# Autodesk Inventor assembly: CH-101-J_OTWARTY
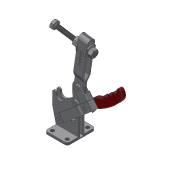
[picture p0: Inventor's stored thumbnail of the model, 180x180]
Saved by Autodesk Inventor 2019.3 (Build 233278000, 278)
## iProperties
Company: Î¢ÈíÖÐ¹ú
Created: 2012-09
Part Number: CH-101-J_OTWARTY
Material: Ogólny
Description: STEP AP203
Document SubType Name: Assembly
Designer: CADENGINEERING4
Sending System: SolidWorks 2010
Preprocessor: SwSTEP 2.0
Title: CH-101-J.STEP
Author: Î¢ÈíÓÃ»§
Revision Number: ÈÎºÎ
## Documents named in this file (16)
- D:\Vault_2016\Projekty\NASZ KATALOG\CLAMPTEK\STRONA\Vertical toggle clamp\CH-101-J\CH-101-J_OTWARTY.iam
- D:\Vault_2016\Projekty\NASZ KATALOG\CLAMPTEK\STEP FILES\Vertical toggle clamp\CH-101-J\CH-101-J-02 U-BAR.ipt
- D:\Vault_2016\Projekty\NASZ KATALOG\CLAMPTEK\STEP FILES\Vertical toggle clamp\CH-101-J\CH-101-J-01 FLANGED BASE.ipt
- D:\Vault_2016\Projekty\NASZ KATALOG\CLAMPTEK\STEP FILES\Vertical toggle clamp\CH-101-J\CH-FW-580.ipt
- D:\Vault_2016\Projekty\NASZ KATALOG\CLAMPTEK\STEP FILES\Vertical toggle clamp\CH-101-J\CH-101-J-06.ipt
- D:\Vault_2016\Projekty\NASZ KATALOG\CLAMPTEK\STEP FILES\Vertical toggle clamp\CH-101-J\CH-101-J-03 HANDLE.ipt
- D:\Vault_2016\Projekty\NASZ KATALOG\CLAMPTEK\STEP FILES\Vertical toggle clamp\CH-101-J\CH-SA-58500 SPINDLE SUPPLIED.ipt
- D:\Vault_2016\Projekty\NASZ KATALOG\CLAMPTEK\STEP FILES\Vertical toggle clamp\CH-101-J\CH-101-J-11.ipt
- D:\Vault_2016\Projekty\NASZ KATALOG\CLAMPTEK\STEP FILES\Vertical toggle clamp\CH-101-J\CH-10247-08.ipt
- D:\Vault_2016\Projekty\NASZ KATALOG\CLAMPTEK\STEP FILES\Vertical toggle clamp\CH-101-J\CH-101-J-07.ipt
- D:\Vault_2016\Projekty\NASZ KATALOG\CLAMPTEK\STEP FILES\Vertical toggle clamp\CH-101-J\CH-10247-05.ipt
- D:\Vault_2016\Projekty\NASZ KATALOG\CLAMPTEK\STEP FILES\Vertical toggle clamp\CH-101-J\CH-101-J-05.ipt
- D:\Vault_2016\Projekty\NASZ KATALOG\CLAMPTEK\STEP FILES\Vertical toggle clamp\CH-101-J\3-8-16 LOCK NUT.ipt
- D:\Vault_2016\Projekty\NASZ KATALOG\CLAMPTEK\STEP FILES\Vertical toggle clamp\CH-101-J\CH-SA-58500 NUT.ipt
- D:\Vault_2016\Projekty\NASZ KATALOG\CLAMPTEK\STEP FILES\Vertical toggle clamp\CH-101-J\CH-101-J-04 CONNECTING-PLATE.ipt
- D:\Vault_2016\Projekty\NASZ KATALOG\CLAMPTEK\STEP FILES\Vertical toggle clamp\CH-101-J\CH-10247-09.ipt
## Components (21 placed, 15 different names)
1. CH-101-J-01 FLANGED BASE_2
2. CH-101-J-05_12
3. CH-10247-09_20
4. CH-101-J-02 U-BAR:2 — Zestawiające:8, Równoległe:1, Zestawiające:14, Zestawiające:26, Zestawiające:27, Zestawiające:32, Zestawiające:33, Zestawiające:37
5. CH-FW-580:3 — Zestawiające:25, Zestawiające:26, Zestawiające:29
6. CH-101-J-06:3 — Zestawiające:13, Zestawiające:39
7. CH-101-J-03 HANDLE:2 — Zestawiające:2, Zestawiające:3, Zestawiające:4, Zestawiające:5, Zestawiające:6, Zestawiające:15, Zestawiające:18, Zestawiające:19, Zestawiające:21, Zestawiające:31, Zestawiające:38
8. CH-SA-58500 SPINDLE SUPPLIED:2 — Zestawiające:22
9. CH-101-J-11:3 — Zestawiające:10, Zestawiające:11, Zestawiające:12, Zestawiające:13, Zestawiające:37
10. CH-10247-08:3 — Zestawiające:1, Zestawiające:3
11. CH-101-J-06:4 — Zestawiające:7, Zestawiające:8, Równoległe:1
12. CH-101-J-07:2 — Zestawiające:1, Zestawiające:2, Zestawiające:6
13. CH-10247-05:2 — Zestawiające:16, Zestawiające:20, Zestawiające:21, Zestawiające:30, Zestawiające:36
14. 3-8-16 LOCK NUT:3 — Zestawiające:17, Zestawiające:18
15. CH-SA-58500 NUT:3 — Zestawiające:24, Zestawiające:25, Zestawiające:29
16. 3-8-16 LOCK NUT:4 — Zestawiające:4, Zestawiające:5
17. CH-101-J-04 CONNECTING-PLATE:2 — Zestawiające:9, Zestawiające:10, Zestawiające:11, Zestawiające:12, Zestawiające:14, Zestawiające:19, Zestawiające:31, Zestawiające:36, Zestawiające:39
18. CH-10247-08:4 — Zestawiające:15, Zestawiające:16, Zestawiające:17, Zestawiające:20, Zestawiające:30, Zestawiające:38
19. CH-FW-580:4 — Zestawiające:23, Zestawiające:27, Zestawiające:28
20. CH-101-J-11:4 — Zestawiające:7, Zestawiające:9
21. CH-SA-58500 NUT:4 — Zestawiające:22, Zestawiające:23, Zestawiające:24, Zestawiające:28, Zestawiające:32, Zestawiające:33
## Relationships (38: Mate 37, Flush 1)
- Zestawiające:1 [Mate]: CH-10247-08:3 ↔ CH-101-J-07:2
- Zestawiające:2 [Mate]: CH-101-J-03 HANDLE:2 ↔ CH-101-J-07:2
- Zestawiające:3 [Mate]: CH-101-J-03 HANDLE:2 ↔ CH-10247-08:3
- Zestawiające:4 [Mate]: CH-101-J-03 HANDLE:2 ↔ 3-8-16 LOCK NUT:4
- Zestawiające:5 [Mate]: CH-101-J-03 HANDLE:2 ↔ 3-8-16 LOCK NUT:4
- Zestawiające:6 [Mate]: CH-101-J-03 HANDLE:2 ↔ CH-101-J-07:2
- Zestawiające:7 [Mate]: CH-101-J-06:4 ↔ CH-101-J-11:4
- Zestawiające:8 [Mate]: CH-101-J-02 U-BAR:2 ↔ CH-101-J-06:4
- Równoległe:1 [Flush]: CH-101-J-02 U-BAR:2 ↔ CH-101-J-06:4
- Zestawiające:9 [Mate]: CH-101-J-04 CONNECTING-PLATE:2 ↔ CH-101-J-11:4
- Zestawiające:10 [Mate]: CH-101-J-11:3 ↔ CH-101-J-04 CONNECTING-PLATE:2
- Zestawiające:11 [Mate]: CH-101-J-11:3 ↔ CH-101-J-04 CONNECTING-PLATE:2
- Zestawiające:12 [Mate]: CH-101-J-11:3 ↔ CH-101-J-04 CONNECTING-PLATE:2
- Zestawiające:13 [Mate]: CH-101-J-06:3 ↔ CH-101-J-11:3
- Zestawiające:14 [Mate]: CH-101-J-02 U-BAR:2 ↔ CH-101-J-04 CONNECTING-PLATE:2
- Zestawiające:15 [Mate]: CH-101-J-03 HANDLE:2 ↔ CH-10247-08:4
- Zestawiające:16 [Mate]: CH-10247-05:2 ↔ CH-10247-08:4
- Zestawiające:17 [Mate]: 3-8-16 LOCK NUT:3 ↔ CH-10247-08:4
- Zestawiające:18 [Mate]: CH-101-J-03 HANDLE:2 ↔ 3-8-16 LOCK NUT:3
- Zestawiające:19 [Mate]: CH-101-J-03 HANDLE:2 ↔ CH-101-J-04 CONNECTING-PLATE:2
- Zestawiające:20 [Mate]: CH-10247-05:2 ↔ CH-10247-08:4
- Zestawiające:21 [Mate]: CH-101-J-03 HANDLE:2 ↔ CH-10247-05:2
- Zestawiające:22 [Mate]: CH-SA-58500 SPINDLE SUPPLIED:2 ↔ CH-SA-58500 NUT:4
- Zestawiające:23 [Mate]: CH-FW-580:4 ↔ CH-SA-58500 NUT:4
- Zestawiające:24 [Mate]: CH-SA-58500 NUT:3 ↔ CH-SA-58500 NUT:4
- Zestawiające:25 [Mate]: CH-FW-580:3 ↔ CH-SA-58500 NUT:3
- Zestawiające:26 [Mate]: CH-101-J-02 U-BAR:2 ↔ CH-FW-580:3
- Zestawiające:27 [Mate]: CH-101-J-02 U-BAR:2 ↔ CH-FW-580:4
- Zestawiające:28 [Mate]: CH-FW-580:4 ↔ CH-SA-58500 NUT:4
- Zestawiające:29 [Mate]: CH-FW-580:3 ↔ CH-SA-58500 NUT:3
- Zestawiające:30 [Mate]: CH-10247-05:2 ↔ CH-10247-08:4
- Zestawiające:31 [Mate]: CH-101-J-03 HANDLE:2 ↔ CH-101-J-04 CONNECTING-PLATE:2
- Zestawiające:32 [Mate]: CH-101-J-02 U-BAR:2 ↔ CH-SA-58500 NUT:4
- Zestawiające:33 [Mate]: CH-101-J-02 U-BAR:2 ↔ CH-SA-58500 NUT:4
- Zestawiające:36 [Mate]: CH-10247-05:2 ↔ CH-101-J-04 CONNECTING-PLATE:2
- Zestawiające:37 [Mate]: CH-101-J-02 U-BAR:2 ↔ CH-101-J-11:3
- Zestawiające:38 [Mate]: CH-101-J-03 HANDLE:2 ↔ CH-10247-08:4
- Zestawiające:39 [Mate]: CH-101-J-06:3 ↔ CH-101-J-04 CONNECTING-PLATE:2
